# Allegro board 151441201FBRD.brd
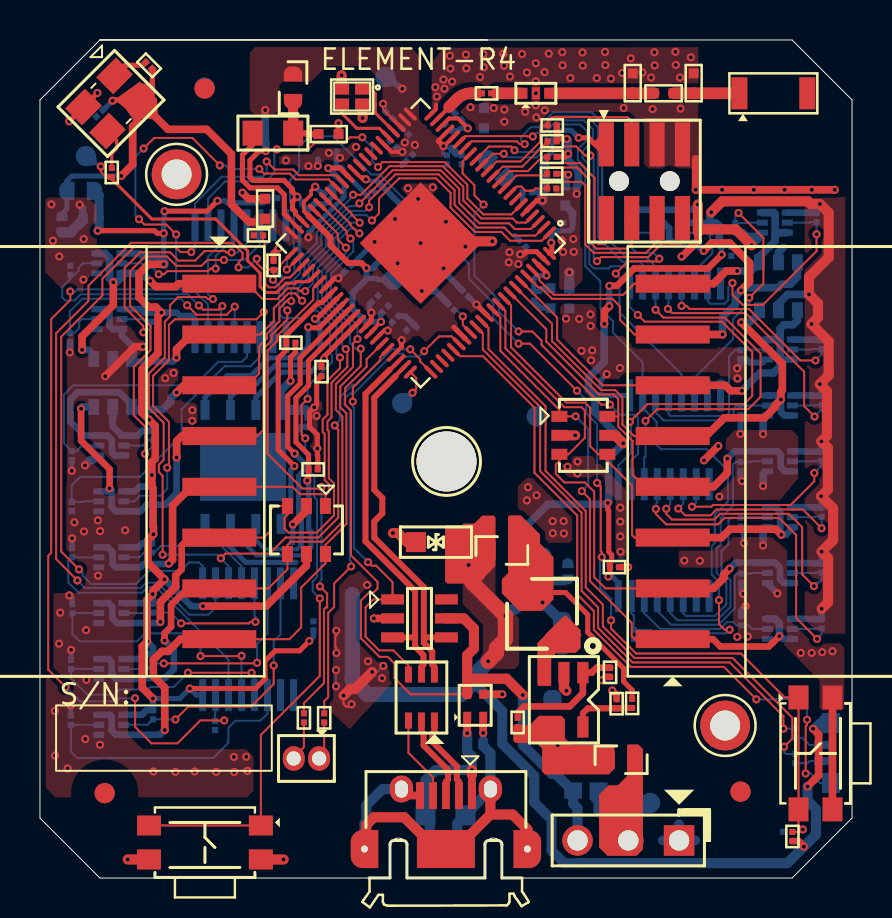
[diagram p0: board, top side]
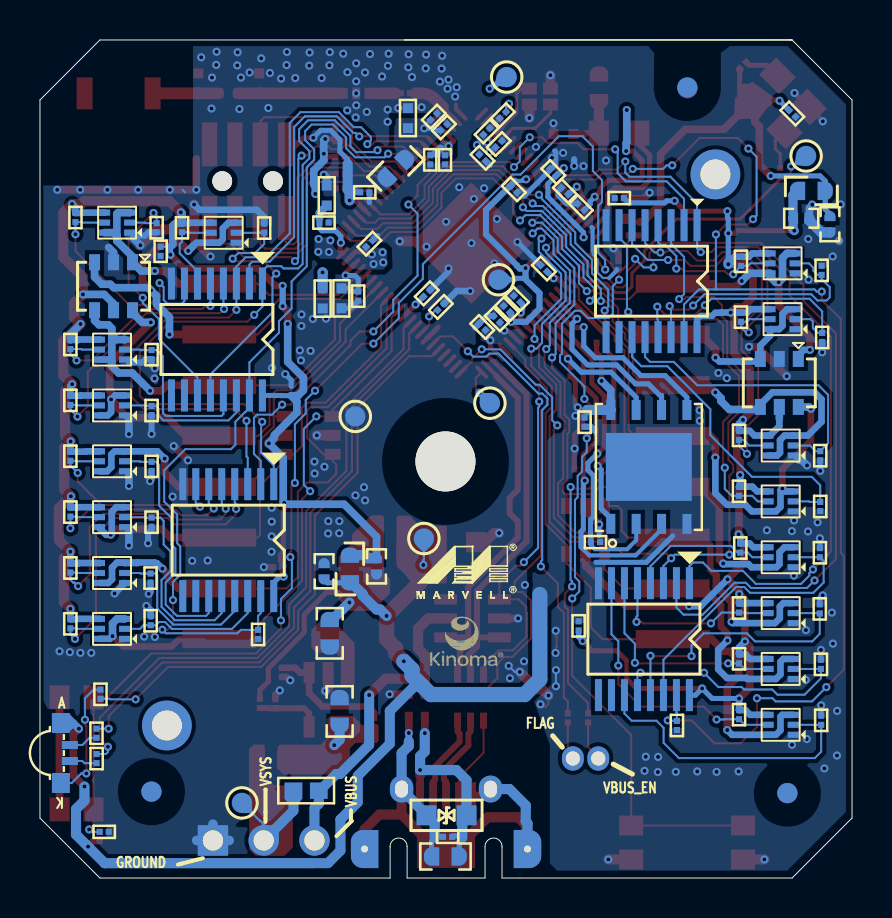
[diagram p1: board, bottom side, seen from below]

Outline 40.64 x 41.92 mm; copper layers: TOP, BOTTOM. Coordinates in mm from the lower left corner of the outline.
Outline path: 3,41.92 0,38.92 0,3 3,0 16.62,0 ; 3,41.92 22.4,41.92 3,41.92 ; 3,41.92 37.64,41.92 40.64,38.92 40.64,3 37.64,0 23.12,0

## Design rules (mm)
net group USB: nets CONN_DM CONN_DP
net group USB_D: nets USB_DM USB_DP

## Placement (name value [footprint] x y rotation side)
ANT1  2450AT18A100  [JOHANSON2450AT18A]  36.7 39.25 0 top
C1  2.2uF  [C0402]  25.55 29 270 bottom
C2  2.2uF  [C0402]  26.29 34.14 90 bottom
C3  0.1uF  [C0201]  24.38 34.3 180 bottom
C4  0.01uF  [C0201]  20.42 37.55 135 bottom
C5  10uF 6.3V X5R  [C0402]  22.23 38.01 90 bottom
C6  0.1uF  [C0201]  17.78 27.95 45 bottom
C7  0.1uF  [C0201]  24.16 31.73 135 bottom
C8  0.1uF  [C0201]  21.28 29.24 135 bottom
C9  0.1uF  [C0201]  16.76 28.97 45 bottom
C10  0.1uF  [C0201]  15.42 30.49 45 bottom
C12  10pF RF  [C0201]  22.35 39.25 180 top
C13  0.1uF  [C0201]  14.95 35.31 45 bottom
C14  0.1uF  [C0201]  18.51 27.57 45 bottom
C15  10uF 6.3V X5R  [C0402]  11.26 33.47 90 top
C16  2.2uF  [C0402]  26.49 28.99 270 bottom
C17  10uF 6.3V X5R  [C0402]  14.44 37.21 0 top
C18  1.0uF  [C0201]  20.37 35.93 270 bottom
C19  0.01uF  [C0201]  13.57 33.56 45 bottom
C20  1.0uF  [C0201]  17.27 28.46 45 bottom
C21  0.01uF  [C0201]  18.49 36.03 225 bottom
C22  0.01uF  [C0201]  17.68 36.71 135 bottom
C23  0.01uF  [C0201]  17.48 38.16 315 bottom
C24  0.1uF  [C0201]  13.38 22.8 270 bottom
C25  0.01uF  [C0201]  18.29 37.35 135 bottom
C26  0.01uF  [C0201]  21.11 35.93 270 bottom
C27  0.1uF  [C0201]  16.92 34.45 225 bottom
C28  0.1uF  [C0201]  14.38 34.37 45 bottom
C29  0.1uF  [C0201]  2.99 38.24 225 bottom
C48  0.1uF  [C0201]  20.24 2.06 180 bottom
C49  10uF 10V X6S  [C0603]  20.35 1.08 270 bottom
C50  4.7uF  [C0603]  25.64 8.33 180 bottom
C51  10uF 6.3V X5R  [C0603]  26.14 12.24 0 bottom
C84  *2.2uF  [C-0402]  26.42 15.34 180 bottom
C85  2.2uF  [C-0402]  23.8 15.59 0 bottom
C86  0.1uF  [C0201]  28.75 15.55 0 top
C87  0.1uF  [C0201]  34.6 31.35 270 bottom
C88  0.1uF  [C0201]  11.65 34.01 0 bottom
C89  0.1uF  [C0201]  13.68 12.61 90 bottom
C90  2.2uF  [C-0402]  2.54 33 270 bottom
C91  *2.2uF  [C-0402]  1.1 32.7 0 bottom
C92  0.1uF  [C0201]  24.71 29.11 270 bottom
C93  0.1uF  [C0201]  26.43 32.78 180 bottom
C94  0.1uF  [C0201]  37.42 2.31 180 bottom
C95  *0.1uF  [C0201]  11.69 30.65 90 top
C96  0.1uF  [C0201]  28.53 10.29 90 top
C98  0.01uF  [C0201]  20.93 38.08 135 bottom
CM1  CMC_2L_60R_600mA  [FIL-2X1_2-4]  21.78 8.64 90 top
CM2  CMC_3L  [TDK2520-3L]  19.09 9.03 90 top
D10  DIODE_LED_RGB_RA  [LED_RGB_RA]  39.54 6.25 270 bottom
FB1  FB/3A  [L-0603]  23.11 16.38 270 top
FB2  FB/3A  [L-0603]  29.09 5.91 90 top
FB7  FB/3A  [L-0603]  25.13 15.46 180 bottom
FB8  FB/3A  [L-0603]  2.03 34.37 90 bottom
FB9  FB/3A  [L-0603]  12.66 39.53 0 top
FB10  FB/3A  [L-0603]  22.83 35.49 45 bottom
FL1  -  [LFB182G45CL3D178]  24.82 39.25 180 top
J1  CON8A  [HDR050_4X2_SMT]  30.25 34.86 0 top
J2  *3PIN  [HDR0_1MILX3]  31.98 1.88 180 top
J3  USB MICRO-AB RCPT  [USB-MICRO-AB_FCI_RCPT_SMD5_RA]  20.32 0 0 top
J6  HDR1x8  [HDR1X8SMD_100MILRA]  31.66 20.84 270 top
J9  HDR1x8  [HDR1X8SMD_100MILRA]  8.98 20.84 90 top
J11  *CON2  [CON2_50]  13.97 5.98 180 top
L1  2.2nH  [L0402]  31.22 39.25 180 top
L2  *2.2nH  [L0402]  32.72 39.75 90 top
L3  2.2uH  [L0805]  11.66 37.26 0 top
L4  2.2uH  [CDRH2D14]  25.13 13.22 180 top
L5  2.2nH  [L0402]  29.67 39.75 90 top
MOV1  CDS305GTA  [D0603]  19.81 16.8 0 top
MOV3  CDS305GTA  [D0603]  20.29 3.14 180 bottom
NOREF  -  [unnamed]  8.24 39.49 0 top
NOREF#2  -  [unnamed]  3.24 4.25 0 top
NOREF#3  -  [unnamed]  34.29 7.63 0 top
NOREF#4  -  [unnamed]  35.06 4.32 0 top
NOREF#5  -  [unnamed]  20.35 20.84 0 top
NOREF#6  -  [#2]  38.95 40.61 0 top
NOREF#7  -  [unnamed]  6.84 35.2 0 top
NOREF#8  -  [unnamed]  35.06 4.32 180 bottom
NOREF#9  -  [unnamed]  8.24 39.54 180 bottom
NOREF#10  -  [unnamed]  3.24 4.25 180 bottom
Q1  FDY4000CZ  [SOT563]  37.03 12.46 0 bottom
Q2  FDY4000CZ  [SOT563]  37.03 15.26 0 bottom
Q3  FDY4000CZ  [SOT563]  37.03 18.05 0 bottom
Q4  FDY4000CZ  [SOT563]  37.03 20.85 0 bottom
Q5  FDY4000CZ  [SOT563]  37.03 23.64 0 bottom
Q6  FDY4000CZ  [SOT563]  37.03 26.43 0 bottom
Q7  FDY4000CZ  [SOT563]  31.45 32.28 0 bottom
Q8  FDY4000CZ  [SOT563]  36.78 32.78 0 bottom
Q9  FDY4000CZ  [SOT563]  3.47 30.75 0 bottom
Q10  FDY4000CZ  [SOT563]  3.48 27.96 0 bottom
Q11  FDY4000CZ  [SOT563]  3.57 21.63 0 bottom
Q12  FDY4000CZ  [SOT563]  3.57 18.84 0 bottom
Q13  FDY4000CZ  [SOT563]  3.57 16.05 0 bottom
Q14  FDY4000CZ  [SOT563]  3.57 13.25 0 bottom
Q15  FDY4000CZ  [SOT563]  3.57 10.46 0 bottom
Q16  FDY4000CZ  [SOT563]  3.57 7.66 0 bottom
R3  6.04k 1%  [R0201]  20.58 28.57 315 bottom
R4  51K  [R0201]  10.94 32.15 0 top
R5  51K  [R0201]  12.56 26.78 180 top
R6  51K  [R0201]  13.67 20.44 180 top
R7  51K  [R0201]  14.09 25.33 90 top
R25  1k  [R0201]  5.46 40.65 135 top
R27  10K  [R-0201]  25.62 36.07 180 top
R28  10K  [R-0201]  25.61 34.49 180 top
R29  10K  [R-0201]  25.63 36.85 180 top
R30  10K  [R-0201]  25.64 37.64 180 top
R36  10K  [R-0201]  25.61 35.23 0 top
R48  330R  [R0201]  37.81 7.24 90 bottom
R49  330R  [R0201]  37.81 5.97 90 bottom
R54  2.2K  [R0201]  37.66 2.08 90 top
R60  0R  [R-0603]  27.32 4.37 0 bottom
R63  10K  [R-0201]  23.91 7.78 90 top
R64  453K  [R0201]  29.63 8.73 270 top
R65  100K  [R0201]  28.86 8.72 90 top
R84  10K  [R-0201]  39.12 15.51 270 bottom
R85  10K  [R-0201]  39.12 18.31 270 bottom
R86  10K  [R-0201]  39.12 21.1 270 bottom
R87  10K  [R-0201]  35.11 15 90 bottom
R88  10K  [R-0201]  35.05 17.8 90 bottom
R89  10K  [R-0201]  35.05 20.59 90 bottom
R90  10K  [R-0201]  39.12 12.72 270 bottom
R91  10K  [R-0201]  35.1 12.87 270 bottom
R92  10K  [R-0201]  39.12 23.89 270 bottom
R93  10K  [R-0201]  39.12 26.69 270 bottom
R94  10K  [R-0201]  33.53 32.53 270 bottom
R95  10K  [R-0201]  38.86 33.04 270 bottom
R96  10K  [R-0201]  35.05 23.39 90 bottom
R97  10K  [R-0201]  35.05 26.18 90 bottom
R98  10K  [R-0201]  29.42 32.51 270 bottom
R99  10K  [R-0201]  34.8 32.53 90 bottom
R100  10K  [R-0201]  29.72 12.18 90 bottom
R101  10K  [R-0201]  5.56 30.85 270 bottom
R102  10K  [R-0201]  5.56 28.05 270 bottom
R103  10K  [R-0201]  5.66 22.14 270 bottom
R104  10K  [R-0201]  5.66 19.35 270 bottom
R105  10K  [R-0201]  1.5 27.04 90 bottom
R106  10K  [R-0201]  1.59 21.13 90 bottom
R107  10K  [R-0201]  1.59 18.59 90 bottom
R108  10K  [R-0201]  1.52 30.4 270 bottom
R109  10K  [R-0201]  5.59 16.51 270 bottom
R110  10K  [R-0201]  5.66 13.51 270 bottom
R111  10K  [R-0201]  5.66 10.97 270 bottom
R112  10K  [R-0201]  5.66 8.17 270 bottom
R113  10K  [R-0201]  1.61 16.27 270 bottom
R114  10K  [R-0201]  1.62 13.46 270 bottom
R115  10K  [R-0201]  1.56 10.69 270 bottom
R116  10K  [R-0201]  1.54 7.89 270 bottom
R117  10K  [R-0201]  8.76 7.63 90 bottom
R118  330R  [R0201]  37.61 9.19 270 bottom
R119  100R  [R0201]  14.22 8.01 90 top
R120  100R  [R0201]  13.21 8.01 90 top
R121  10K  [R-0201]  12.84 16.8 180 bottom
R128  22R  [R0201]  3.59 35.29 90 top
S1  SW_PB_RA_4P  [SW_WE_SPST_4P]  8.25 1.78 0 top
S2  SW_PB_RA_4P  [SW_WE_SPST_4P]  38.81 6.23 90 top
TP1  *T_POINT  [TP040]  30.53 3.76 180 bottom
TP2  *T_POINT  [TP040]  21.43 16.98 90 bottom
TP3  *T_POINT  [TP040]  24.86 23.09 180 bottom
TP4  *T_POINT  [TP040]  18.12 23.75 180 bottom
TP5  *T_POINT  [TP040]  2.3 36.12 180 bottom
TP6  *T_POINT  [TP040]  17.69 29.93 135 bottom
TP7  *T_POINT  [TP040]  17.28 40.07 135 bottom
U1  88MW302QFN88  [MRVL_QFN88LP40_10X10_NXU]  19.05 31.76 225 top
U2  W25Q32FVZPIG  [IC_WBOND_WSON8_ZP]  10.17 20.56 90 bottom
U7  AP3417C  [SOT23-5]  26.22 8.91 90 top
U8  IP4220CZ6  [IC_NXP_TSOP6]  18.99 12.99 270 top
U13  74HC4094  [TSSOP16]  31.22 16.9 0 bottom
U14  74HC4094  [TSSOP16]  31.78 26.94 0 bottom
U15  D5V0F4U6SO-7  [SC-74]  27.19 22.14 270 top
U16  D5V0F4U6SO-7  [SC-74]  36.96 29.6 0 bottom
U17  74HC4094  [TSSOP16]  10.03 29.86 0 bottom
U18  74HC4094  [TSSOP16]  10.41 11.95 0 bottom
U19  D5V0F4U6SO-7  [SC-74]  3.64 24.76 0 bottom
U20  D5V0F4U6SO-7  [SC-74]  13.34 17.41 180 top
Y1  38.4MHz +/-10ppm  [XTAL_TXC_SMD_1_6X1_2MM]  15.62 39.09 180 top
Y2  32.768KHz_3.3V_+/-25ppm  [XOSC_TXC_SMD_3_2X2_5MM]  3.56 38.75 225 top

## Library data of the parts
ANT1 = chip antenna
C1-C10 C12-C29 C48 C49 C86-C89 C92-C96 C98 = CAP_NP
C50 C51 = CAP NP_0
C84 C85 C90 C91 = CAP NP_2
CM1 = CMC_2L_1-2_3-4
CM2 = CMC_3L
D10 = DIODE_LED_RGB_RA
FB1 FB2 FB7-FB10 = FERRITE_BEAD_0
FL1 = RF_DEA162450BT-1298A1
J1 = CON8A
J2 = CON3
J3 = CON_MOLEX_USB-MICRO-AB_SMD
J6 J9 = CON8
J11 = CON2
L1-L5 = INDUCTOR
MOV1 MOV3 = MOV-small
Q1-Q16 = CMOS-DUAL
R3-R7 R25 R27-R30 R36 R48 R49 R54 R63-R65 R118-R120 R128 = RES
R60 R84-R99 R101-R116 = R_0
R100 R117 R121 = Res_0
S1 S2 = SW_PB_RA_4P
TP1-TP7 = T_POINT
U1 = 88MW302_QFN88L_1
U2 = IC_WBOND_SPI_FLASH_DQIO_WSON8
U7 = AP3417C
U8 = IC_NXP_IP4220CZ6_TSOP6
U13 U14 U17 U18 = 74HC4094
U15 U16 U19 U20 = CM1293A
Y1 = XTAL_TXC_SMD_1.6X1.2MM
Y2 = XOSC_TXC_3.2X2.5MM: Tolerance: TOL; User Part Number: 5044-001-002357

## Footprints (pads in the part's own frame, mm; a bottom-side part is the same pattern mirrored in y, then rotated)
C0201
  rect 0.305x0.305 smd: 1(-0.229,0) 2(0.229,0)
C0402
  rect 0.5x0.5 smd: 1(-0.5,0) 2(0.5,0)
C0603
  custom 0.191x0.191 smd: 1(0,-0.691) 2(0,0.691)
C-0402
  custom 0.126x0.126 smd: 1(0,-0.409) 2(0,0.409)
CDRH2D14
  rect 1.3x1.3 smd rot 45: 1(-1.061,1.061) 2(1.061,-1.061)
CON2_50
  oval 1.092x1.219 hole 0.711: 1(0,0) 2(1.27,0)
D0603
  rect 1.001x1.001 smd: 1(-1.001,0) 2(1.001,0)
FIL-2X1_2-4
  rect 0.45x0.4 smd: 1(-0.55,0.4) 2(0.55,0.4) 3(0.55,-0.4) 4(-0.55,-0.4)
HDR0_1MILX3
  rect 1.524x1.524 hole 1.016: 1(0,0)
  round 1.524 hole 1.016: 2(2.54,0) 3(5.08,0)
HDR1X8SMD_100MILRA
  rect 0.9x3.7 smd: 1(8.89,0) 2(6.35,0) 3(3.81,0) 4(1.27,0) 5(-1.27,0) 6(-3.81,0) 7(-6.35,0) 8(-8.89,0)
HDR050_4X2_SMT
  round 0.991 hole 0.991 unplated: (-1.27,0) (1.27,0)
  rect 0.76x2.2 smd: 1(-1.905,1.841) 2(-1.905,-1.841) 3(-0.635,1.841) 4(-0.635,-1.841) 5(0.635,1.841) 6(0.635,-1.841) 7(1.905,1.841) 8(1.905,-1.841)
IC_NXP_TSOP6
  rect 0.508x1.143 smd: 1(-0.95,-1.349) 2(0,-1.349) 3(0.95,-1.349) 4(0.95,1.349) 5(0,1.349) 6(-0.95,1.349)
IC_WBOND_WSON8_ZP
  rect 1x0.45 smd: 1(-2.85,1.905) 2(-2.85,0.635) 3(-2.85,-0.635) 4(-2.85,-1.905) 5(2.85,-1.905) 6(2.85,-0.635) 7(2.85,0.635) 8(2.85,1.905)
  rect 3.4x4.3 smd: 9(0,0)
JOHANSON2450AT18A
  rect 0.8x1.6 smd: 1(-1.7,0) 2(1.7,0)
L0402
  rect 0.5x0.5 smd: 1(-0.5,0) 2(0.5,0)
L0805
  rect 1.001x1.25 smd: 1(-1.016,0) 2(1.016,0)
L-0603
  custom 0.191x0.191 smd: 1(0,-0.691) 2(0,0.691)
LED_RGB_RA
  rect 1.001x0.899 smd: 1(1.5,-0.05) 2(-1.5,-0.05)
  rect 0.399x0.8 smd: 3(-0.4,0.4) 4(0.4,0.4)
LFB182G45CL3D178
  rect 0.28x0.55 smd: 1(0.56,0) 3(-0.56,0)
  rect 0.4x0.6 smd: 2(0,0)
MRVL_QFN88LP40_10X10_NXU
  oval 0.85x0.2 smd: 1(-4.925,4.2) 2(-4.925,3.8) 3(-4.925,3.4) 4(-4.925,3) 5(-4.925,2.6) 6(-4.925,2.2) 7(-4.925,1.8) 8(-4.925,1.4) 9(-4.925,1) 10(-4.925,0.6) 11(-4.925,0.2) 12(-4.925,-0.2) 13(-4.925,-0.6) 14(-4.925,-1) 15(-4.925,-1.4) 16(-4.925,-1.8) 17(-4.925,-2.2) 18(-4.925,-2.6) 19(-4.925,-3) 20(-4.925,-3.4) 21(-4.925,-3.8) 22(-4.925,-4.2) 45(4.925,-4.2) 46(4.925,-3.8) 47(4.925,-3.4) 48(4.925,-3) 49(4.925,-2.6) 50(4.925,-2.2) 51(4.925,-1.8) 52(4.925,-1.4) 53(4.925,-1) 54(4.925,-0.6) 55(4.925,-0.2) 56(4.925,0.2) 57(4.925,0.6) 58(4.925,1) 59(4.925,1.4) 60(4.925,1.8) 61(4.925,2.2) 62(4.925,2.6) 63(4.925,3) 64(4.925,3.4) 65(4.925,3.8) 66(4.925,4.2)
  oval 0.2x0.85 smd: 23(-4.2,-4.925) 24(-3.8,-4.925) 25(-3.4,-4.925) 26(-3,-4.925) 27(-2.6,-4.925) 28(-2.2,-4.925) 29(-1.8,-4.925) 30(-1.4,-4.925) 31(-1,-4.925) 32(-0.6,-4.925) 33(-0.2,-4.925) 34(0.2,-4.925) 35(0.6,-4.925) 36(1,-4.925) 37(1.4,-4.925) 38(1.8,-4.925) 39(2.2,-4.925) 40(2.6,-4.925) 41(3,-4.925) 42(3.4,-4.925) 43(3.8,-4.925) 44(4.2,-4.925) 67(4.2,4.925) 68(3.8,4.925) 69(3.4,4.925) 70(3,4.925) 71(2.6,4.925) 72(2.2,4.925) 73(1.8,4.925) 74(1.4,4.925) 75(1,4.925) 76(0.6,4.925) 77(0.2,4.925) 78(-0.2,4.925) 79(-0.6,4.925) 80(-1,4.925) 81(-1.4,4.925) 82(-1.8,4.925) 83(-2.2,4.925) 84(-2.6,4.925) 85(-3,4.925) 86(-3.4,4.925) 87(-3.8,4.925) 88(-4.2,4.925)
  rect 4.3x4.3 smd: 89(0,0)
R0201
  rect 0.305x0.305 smd: 1(-0.229,0) 2(0.229,0)
R-0201
  rect 0.305x0.305 smd: 1(-0.229,0) 2(0.229,0)
R-0603
  rect 0.889x0.813 smd: 1(-0.635,0) 2(0.635,0)
SC-74
  rect 0.55x0.8 smd: 1(-0.95,-1.2) 2(0,-1.2) 3(0.95,-1.2) 4(0.95,1.2) 5(0,1.2) 6(-0.95,1.2)
SOT23-5
  rect 1.069x0.559 smd: 1(1.359,-0.95) 2(1.359,0) 3(1.359,0.95) 4(-1.359,0.95) 5(-1.359,-0.95)
SOT563
  rect 0.55x0.305 smd: 1(-0.625,0.5) 2(-0.625,0) 3(-0.625,-0.5) 4(0.625,-0.5) 5(0.625,0) 6(0.625,0.5)
SW_WE_SPST_4P
  rect 1.2x1 smd: 1(2.8,0.85) 2(-2.8,0.85) 3(2.8,-0.85) 4(-2.8,-0.85)
TDK2520-3L
  rect 0.8x0.35 smd: 1(-1.151,-0.65) 2(-1.151,0) 3(-1.151,0.65) 4(1.151,0.65) 5(1.151,0) 6(1.151,-0.65)
TP040
  round 1.016 smd: 1(0,0)
TSSOP16
  rect 0.35x1.6 smd: 1(-2.276,-2.799) 2(-1.626,-2.799) 3(-0.975,-2.799) 4(-0.325,-2.799) 5(0.325,-2.799) 6(0.975,-2.799) 7(1.626,-2.799) 8(2.276,-2.799) 9(2.276,2.799) 10(1.626,2.799) 11(0.975,2.799) 12(0.325,2.799) 13(-0.325,2.799) 14(-0.975,2.799) 15(-1.626,2.799) 16(-2.276,2.799)
unnamed
  round 1.016 smd: (0,0)
USB-MICRO-AB_FCI_RCPT_SMD5_RA
  rect 0.399x1.349 smd: 1(1.301,4.125) 2(0.65,4.125) 3(0,4.125) 4(-0.65,4.125) 5(-1.301,4.125)
  oval 1.168x1.346 hole 0.65x0.851: 6(-2.225,4.45) 7(2.225,4.45)
  custom 0.344x0.344 hole 0.8x1.5: 8(-4.075,1.45) 9(4.075,1.45)
  rect 2.901x1.9 smd: 10(0,1.45)
XOSC_TXC_SMD_3_2X2_5MM
  rect 1.4x1.2 smd: 1(-1.1,-0.85) 2(1.1,-0.85) 3(1.1,0.85) 4(-1.1,0.85)
XTAL_TXC_SMD_1_6X1_2MM
  rect 0.75x0.6 smd: 1(-0.526,-0.399) 2(0.526,-0.399) 3(0.526,0.399) 4(-0.526,0.399)

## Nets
GND: C1.2 C2.2 C3.2 C4.2 C5.2 C6.2 C7.2 C8.2 C9.2 C10.2 C13.2 C14.2 C15.2 C16.2 C17.2 C18.2 C19.2 C20.2 C21.2 C22.2 C23.2 C24.2 C25.2 C26.2 C27.2 C28.2 C29.2 C50.2 C51.2 C84.2 C85.2 C86.2 C87.2 C88.2 C89.2 C90.2 C91.2 C92.2 C93.2 C94.2 C95.2 C96.1 C98.2 CM1.3(OUT2) FL1.2(GND) J1.5 J1.7 J2.1 L2.2 L5.2 MOV1.1 Q1.1(S) Q2.1(S) Q3.1(S) Q4.1(S) Q5.1(S) Q6.1(S) Q7.1(S) Q8.1(S) Q9.1(S) Q10.1(S) Q11.1(S) Q12.1(S) Q13.1(S) Q14.1(S) Q15.1(S) Q16.1(S) R3.1 R36.2 R65.2 R87.1 R88.1 R89.1 R91.1 R96.1 R97.1 R98.1 R99.1 R100.1 R105.1 R106.1 R107.1 R108.1 R113.1 R114.1 R115.1 R116.1 R117.1 R121.2 S1.3 S1.4 S2.3 S2.4 TP3.1(TP) U1.22(NC) U1.89(EPAD) U2.4(GND) U2.9(EPAD) U7.2(GND) U8.2(GND) U13.8(GND) U14.8(GND) U15.2(NV) U16.2(NV) U17.8(GND) U18.8(GND) U19.2(NV) U20.2(NV) Y1.2(GND#2) Y1.4(GND#4) Y2.2(GND)
GND_EN1: Q1.2(G) R91.2 U13.14(QP4)
GND_EN2: Q2.2(G) R87.2 U13.13(QP5)
GND_EN3: Q3.2(G) R88.2 U13.12(QP6)
GND_EN4: Q4.2(G) R89.2 U13.11(QP7)
GND_EN5: Q5.2(G) R96.2 U14.14(QP4)
GND_EN6: Q6.2(G) R97.2 U14.13(QP5)
GND_EN7: Q7.2(G) R98.2 U14.12(QP6)
GND_EN8: Q8.2(G) R99.2 U14.11(QP7)
GND_EN9: Q9.2(G) R108.2 U17.14(QP4)
GND_EN10: Q10.2(G) R105.2 U17.13(QP5)
GND_EN11: Q11.2(G) R106.2 U17.12(QP6)
GND_EN12: Q12.2(G) R107.2 U17.11(QP7)
GND_EN13: Q13.2(G) R113.2 U18.14(QP4)
GND_EN14: Q14.2(G) R114.2 U18.13(QP5)
GND_EN15: Q15.2(G) R115.2 U18.12(QP6)
GND_EN16: Q16.2(G) R116.2 U18.11(QP7)
GND_OTG_CONN: C48.1 C49.1 CM1.4(IN2) J3.5(GND) J3.6(SHIELD1) J3.7(SHIELD2) J3.8(SHIELD3) J3.9(SHIELD4) J3.10(SHIELD5) MOV3.1
V1P1: C20.1 C27.1 C28.1 TP6.1(TP) U1.33(VDD11#33) U1.41(LDO11_VOUT) U1.59(VDD11#59)
V1P8: C18.1 C19.1 C21.1 C22.1 C23.1 C25.1 C26.1 FB9.2 TP7.1(TP) U1.18(AVDD18#18) U1.19(AVDD18#19) U1.23(AVDD18#23) U1.24(AVDD18#24) U1.25(AVDD18#25) U1.28(AVDD18#28) U1.42(LDO11_V18)
V1P8O: C17.1 FB9.1 L3.2
V3P3: C3.1 C6.1 C7.1 C8.1 C9.1 C10.1 C13.1 C14.1 C15.1 C16.1 C24.1 C29.1 C84.1 C91.1 D10.2(ANODE) FB1.1 FB7.1 FB8.1 FB10.2 J1.1 MOV1.2 R4.1 R5.1 R6.1 R7.1 R25.1 R27.1 R28.1 R29.1 R30.1 R54.1 TP2.1(TP) U1.5(VDDIO_0) U1.34(VDDIO_1) U1.44(VBAT_IN#44) U1.51(VDDIO_AON) U1.58(VDDIO_2) U1.60(VTR_VDD33) U1.63(USB_AVDD33) U1.73(VDDIO_3#73) U1.77(VDDIO_3#77) U1.87(VBAT_IN#87) U2.8(VCC) Y2.4(VDD)
V3P3_EN: C96.2 R63.2 U7.1(EN)
V3P3_FB: R64.2 R65.1 U7.5(FB)
V3P3_OUT: C51.1 FB1.2 L4.2 R64.1
V5P0_VIN: C50.1 FB2.2 R63.1 U7.4(VIN)
VBUS_OTG: CM1.2(OUT1) J2.3 R60.1 U1.61(USB_VBUS) U8.5(VP)
VBUS_OTG_CONN: C48.2 C49.2 CM1.1(IN1) J3.1(VBUS) MOV3.2
VCC_FLEX1: C85.1 C86.1 C87.1 FB7.2 Q1.4(S) Q2.4(S) Q3.4(S) Q4.4(S) Q5.4(S) Q6.4(S) Q7.4(S) Q8.4(S) R84.1 R85.1 R86.1 R90.1 R92.1 R93.1 R94.1 R95.1 U13.16(VCC) U14.16(VCC) U15.5(VP) U16.5(VP)
VCC_FLEX2: C88.1 C89.1 C90.1 FB8.2 Q9.4(S) Q10.4(S) Q11.4(S) Q12.4(S) Q13.4(S) Q14.4(S) Q15.4(S) Q16.4(S) R101.1 R102.1 R103.1 R104.1 R109.1 R110.1 R111.1 R112.1 U17.16(VCC) U18.16(VCC) U19.5(VP) U20.5(VP)
VDD11_F_88: C2.1 C93.1 U1.88(FLY11)
VDD18_F_86: C1.1 C92.1 U1.86(FLY18)
VDD33_20: C4.1 C5.1 C98.1 FB10.1 U1.20(AVDD33)
CLK32K: R128.2 Y2.3(OUT)
CONN_DM: CM2.1(IN1) J3.2(D-)
CONN_DP: CM2.2(OUT1) J3.3(D+)
CONN_ID: CM2.3(OUT2) J3.4(ID)
CP1: U1.16(GPIO_14) U13.3(CP) U14.3(CP)
CP2: U1.67(GPIO_34) U17.3(CP) U18.3(CP)
D_1_4: U1.15(GPIO_13) U13.2(D)
D_5_8: U1.17(GPIO_15) U14.2(D)
D_9_12: U1.6(GPIO_4) U17.2(D)
D_13_16: U1.47(GPIO_23) U18.2(D)
EN_32K: R25.2 Y2.1(EC)
GPIO_5: U1.7(GPIO_5)
GPIO_24: U1.48(GPIO_24)
GPIO_25: R128.1 TP5.1(TP) U1.49(GPIO_25)
GPIO_27: TP4.1(TP) U1.66(GPIO_27)
GPIO_35: U1.68(GPIO_35)
GPIO_36: U1.69(GPIO_36)
GPIO_37: U1.70(GPIO_37)
ISENSE: R3.2 U1.74(ISENSE)
LED1: R48.2 U1.75(GPIO_40)
LED2: R49.2 U1.76(GPIO_41)
LED3: R118.2 U1.71(GPIO_38)
MCI_TCK: J1.4 R36.1 U1.9(GPIO_7)
MCI_TDI: J1.8 R29.2 U1.11(GPIO_9)
MCI_TDO: J1.6 R28.2 U1.8(GPIO_6)
MCI_TMS: J1.2 R27.2 U1.10(GPIO_8)
MCI_TRST: J1.3 R30.2 U1.12(GPIO_10)
OE1: R100.2 U1.13(GPIO_11) U13.15(OE) U14.15(OE)
OE2: R117.2 U1.36(GPIO_17) U17.15(OE) U18.15(OE)
PIN1: J6.1 Q1.3(D) Q1.6(D) U1.78(GPIO_42) U15.1(CH1)
PIN2: J6.2 Q2.3(D) Q2.6(D) U1.79(GPIO_43) U15.3(CH2)
PIN3: J6.3 Q3.3(D) Q3.6(D) U1.80(GPIO_44) U15.4(CH3)
PIN4: J6.4 Q4.3(D) Q4.6(D) U1.81(GPIO_45) U15.6(CH4)
PIN5: J6.5 Q5.3(D) Q5.6(D) U1.82(GPIO_46) U16.6(CH4)
PIN6: J6.6 Q6.3(D) Q6.6(D) U1.83(GPIO_47) U16.4(CH3)
PIN7: J6.7 Q7.3(D) Q7.6(D) U1.84(GPIO_48) U16.3(CH2)
PIN8: J6.8 Q8.3(D) Q8.6(D) U1.85(GPIO_49) U16.1(CH1)
PIN9: J9.1 Q9.3(D) Q9.6(D) U1.1(GPIO_0) U19.1(CH1)
PIN10: J9.2 Q10.3(D) Q10.6(D) U1.2(GPIO_1) U19.3(CH2)
PIN11: J9.3 Q11.3(D) Q11.6(D) U1.3(GPIO_2) U19.4(CH3)
PIN12: J9.4 Q12.3(D) Q12.6(D) U1.4(GPIO_3) U19.6(CH4)
PIN13: J9.5 Q13.3(D) Q13.6(D) U1.37(GPIO_18) U20.1(CH1)
PIN14: J9.6 Q14.3(D) Q14.6(D) U1.38(GPIO_19) U20.3(CH2)
PIN15: J9.7 Q15.3(D) Q15.6(D) U1.39(GPIO_20) U20.4(CH3)
PIN16: J9.8 Q16.3(D) Q16.6(D) U1.40(GPIO_21) U20.6(CH4)
PWR_EN1: Q1.5(G) R90.2 U13.4(QP0)
PWR_EN2: Q2.5(G) R84.2 U13.5(QP1)
PWR_EN3: Q3.5(G) R85.2 U13.6(QP2)
PWR_EN4: Q4.5(G) R86.2 U13.7(QP3)
PWR_EN5: Q5.5(G) R92.2 U14.4(QP0)
PWR_EN6: Q6.5(G) R93.2 U14.5(QP1)
PWR_EN7: Q7.5(G) R94.2 U14.6(QP2)
PWR_EN8: Q8.5(G) R95.2 U14.7(QP3)
PWR_EN9: Q9.5(G) R101.2 U17.4(QP0)
PWR_EN10: Q10.5(G) R102.2 U17.5(QP1)
PWR_EN11: Q11.5(G) R103.2 U17.6(QP2)
PWR_EN12: Q12.5(G) R104.2 U17.7(QP3)
PWR_EN13: Q13.5(G) R109.2 U18.4(QP0)
PWR_EN14: Q14.5(G) R110.2 U18.5(QP1)
PWR_EN15: Q15.5(G) R111.2 U18.6(QP2)
PWR_EN16: Q16.5(G) R112.2 U18.7(QP3)
QSPI_CLK: U1.53(GPIO_29) U2.6(CLK)
QSPI_D0: U1.54(GPIO_30) U2.5(DI)
QSPI_D1: R121.1 U1.55(GPIO_31) U2.2(DO)
QSPI_D2: R6.2 U1.56(GPIO_32) U2.3(W\P\)
QSPI_D3: R7.2 U1.57(GPIO_33) U2.7(H\O\L\D\)
QSPI_SSN: R5.2 U1.52(GPIO_28) U2.1(C\S\)
RESETN: C95.1 R4.2 S1.1 S1.2 U1.45(RESETN)
RF_TX-RX: C12.2 U1.21(RF_TR)
STR1: U1.14(GPIO_12) U13.1(STR) U14.1(STR)
STR2: U1.35(GPIO_16) U17.1(STR) U18.1(STR)
SW3P3: L4.1 U7.3(LX)
USB_DM: CM2.6(IN6) U1.65(USB_DM) U8.4(IO3)
USB_DP: CM2.5(IN5) U1.64(USB_DP) U8.3(IO2)
USB_DRVBUS: R120.2 U1.50(GPIO_26)
USB_ID: CM2.4(IN2) U1.62(USB_ID) U8.1(IO1)
USB_OTG_POWER_FAULT: R119.2 U1.72(GPIO_39)
VSYS_IN: FB2.1 J2.2 R60.2 TP1.1(TP)
WAKEUP0: C94.1 R54.2 S2.1 S2.2 U1.46(GPIO_22)
XTAL_IN: U1.26(XTAL_IN) Y1.1(IN)
XTAL_OUT: U1.27(XTAL_OUT) Y1.3(OUT)
N04866: L3.1 U1.43(BUCK18_VX)
N14504: C12.1 FL1.1(IN)
N14557: ANT1.1 L1.1 L2.1
N16809573: D10.4(B) R49.1
N16809863: D10.1(R) R118.1
N16809865: D10.3(G) R48.1
N16909824: J11.1 R119.1
N16909825: J11.2 R120.1
N16943358: FL1.3(OUT) L1.2 L5.1

Pads without a net: ANT1 2; U1 29 30 31 32; U8 6; U13 9 10; U14 9 10; U17 9 10; U18 9 10

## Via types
v1: diameter 0.406, hole 0.203, TOP to BOTTOM, 433 vias

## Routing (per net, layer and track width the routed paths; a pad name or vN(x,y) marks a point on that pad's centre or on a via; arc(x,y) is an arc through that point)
GND: length 95
  TOP w0.102: v1(15.19,9.13) 15.19,8.71 15.34,8.56 15.46,8.56 v1(15.59,8.69) ; v1(14.83,12.37) 14.83,12.12 14.78,12.07 14.78,11.57 14.84,11.51 v1(14.84,11.26) ; 32.79,36 32.82,35.98 ; v1(16.63,10.31) 16.73,10.31
  TOP w0.203: U1.22 19.82,38.47 19.82,38.69
  TOP w0.254: R36.2 26.39,35.23 v1(26.44,35.18) ; v1(1.46,37.85) Y2.2 v1(2.88,39.27)
  TOP w0.305: C17.2 v1(14.94,37.76) ; v1(11.94,31.5) 11.69,31.25 C95.2
  TOP w0.33: R65.2 28.86,9.16 v1(28.64,9.38) ; C96.1 28.52,10.06 28.29,10.06 v1(28.12,9.89) ; C86.2 v1(29.44,15.55)
  TOP w0.381: CM1.3 v1(23.14,9.19) ; 32.93,32.31 32.93,31.85 32.91,31.85 32.14,31.09 v1(32.11,31.09) ; C15.2 10.44,33.97 v1(10.13,34.28) ; v1(39.78,34.43) v1(38.63,34.43) v1(37.26,34.43) v1(35.73,34.43) v1(34.14,34.43) v1(32.82,34.43) 32.82,35.98 ; U8.2 v1(16.71,12.99) ; S2.4 S2.3 ; v1(33.23,20.89) v1(33.95,21.61) ; v1(12.66,17.69) 13.34,18.36 U20.2 ; v1(5.15,26.58) 4.74,26.58 v1(3.27,25.1)
  TOP w0.5: MOV1.1 18.37,16.8 17.92,17.26 v1(17.66,17.26)
  TOP w0.508: v1(26.35,9.37) 26.22,9.49 U7.2 ; v1(35.61,31.65) 34.82,32.45 33.06,32.45 32.93,32.31 v1(32.93,33.69) ; S1.4 v1(4.39,0.93) ; v1(22.63,31.85) 21.56,31.85 v1(21.29,31.58) ; Y1.2 v1(15.1,40.16) ; U15.2 v1(26.78,22.14) ; S1.3 v1(12.19,0.93) ; Y1.4 v1(16.15,38.02) ; v1(16.63,10.31) 15.77,9.45 15.52,9.45 v1(15.19,9.13)
  BOTTOM w0.102: 16.43,34.1 16.42,34.1 ; 12.98,31.34 12.98,31.34 12.98,31.19 12.74,30.95 12.74,30.29 12.46,30.01 12.16,30.01 ; v1(16.63,10.31) 16.88,10.31 v1(17.18,10.61) ; v1(23.24,38.44) 23.27,38.41 ; 16.67,34.42 16.55,34.42 16.47,34.34 ; 21.67,38.59 21.59,38.67 ; 14.89,36.37 14.8,36.46 ; 33.51,34.43 33.38,34.3 ; v1(14.82,9.59) v1(14.82,10.4) ; 24.13,33.77 24.16,33.79 ; 8.97,17.12 8.91,17.12
  BOTTOM w0.203: 12.16,30.01 11.77,30.39 11.77,30.46 ; 13.04,32.57 12.98,32.51 12.98,31.34
  BOTTOM w0.254: 28.07,24.58 28.07,24.91 v1(28.36,25.21) ; v1(1.47,14.14) 1.62,13.99 R114.1 ; 14.73,34.16 14.29,33.73 C19.2 ; R113.1 v1(1.61,16.99) ; C10.2 v1(16.75,31.82) ; 14.57,34.49 14.73,34.33 ; C92.2 25.09,28.5 C1.2 ; 18.11,35.64 18.11,35.65 C21.2 ; 12.66,17.13 v1(12.66,17.69) ; 24.16,33.79 C3.2 ; R106.1 v1(1.59,20.37) ; 16.42,34.1 14.82,35.69 14.82,36.31 14.89,36.37 ; 8.97,17.12 10.29,15.79 12.82,15.79 ; R115.1 v1(1.56,11.41) ; C7.2 23.75,32.14 ; R116.1 v1(1.54,8.64)
  BOTTOM w0.305: R87.1 35.11,14.31 v1(35.2,14.21) ; 18.67,27.73 C14.2 ; 18.67,27.73 18.28,28.11 C6.2 ; 18.67,27.73 18.86,27.54 ; 13.91,35.95 v1(13.91,35.62) ; v1(34.89,25.5) 35.05,25.66 R97.1 35.36,25.95 35.53,25.78 36.19,25.78 ; R89.1 35.05,19.93 v1(35.13,19.86) ; 12.87,22.37 13.08,22.57 C24.2 ; v1(20.2,30.49) 20.2,30.33 20.92,29.61 20.92,29.6 C8.2 ; R88.1 35.05,17.43 35.23,17.25 v1(35.23,16.75) ; R99.1 35.21,32.3 35.38,32.13 35.93,32.13 ; v1(35.05,22.21) R96.1
  BOTTOM w0.33: Q2.1 36.41,14.73 v1(36.91,14.23) ; v1(35.32,13.61) 35.1,13.39 R91.1 ; R105.1 v1(1.5,26.29) ; R3.1 19.79,29.36 v1(19.11,29.36) ; R98.1 29.42,33.06 29.79,33.43 32.67,33.43 v1(32.93,33.69)
  BOTTOM w0.381: C90.2 2.13,33.51 1.99,33.65 v1(1.99,33.68) ; 36.19,20.2 v1(36.19,19.61) ; v1(2.25,20.64) 2.53,20.92 2.66,20.92 2.72,20.98 ; 36.19,22.99 v1(36.19,22.21) ; v1(26.44,35.18) 26.29,35.03 C2.2 ; 37.21,31.55 36.96,31.3 U16.2 ; 36.19,17.4 v1(36.19,16.63) ; v1(35.61,31.65) 35.93,31.97 35.93,32.13
  BOTTOM w0.483: J2.1 31.98,2.69 ; J2.1 32.8,1.88 ; J2.1 31.17,1.88
  BOTTOM w0.508: C90.2 2.13,32.89 1.53,32.29 1.11,32.29 C91.2
  vias: v1(0.57,33.7) v1(0.65,31.87) v1(0.74,8.36) v1(0.75,6.13) v1(0.97,31.09) v1(1.01,13.28) v1(0.95,11.72) v1(1.38,5.48) v1(1.72,17.79) v1(2.19,31.97) v1(2.18,29.93) v1(2.2,17.34) v1(2.31,12.4) v1(2.32,9.91) v1(2.27,6.95) v1(2.9,17.89) v1(2.91,15.12) v1(3.01,17.35) v1(3,6.66) v1(4.26,17.4) v1(5.68,5.33) v1(6.27,25) v1(6.69,25.27) v1(6.78,5.31) v1(7.63,23.4) v1(7.61,22.87) v1(7.75,5.33) v1(8.82,5.31) v1(9.71,6.06) v1(9.72,5.3) v1(10.32,6.07) v1(10.38,5.36) v1(12.31,35.89) v1(13.44,35.61) v1(14.46,36.27) v1(15.02,36.02) v1(15.82,36.57) v1(16.37,14.66) v1(16.42,10.84) v1(17.12,10) v1(17.77,32.97) v1(17.9,30.75) v1(18.41,34.5) v1(18.92,33.97) v1(19.05,31.76) v1(19.66,34.55) v1(19.79,39.56) v1(19.86,39.09) v1(20.19,39.94) v1(20.24,39.48) v1(20.32,32.83) v1(20.51,41.13) v1(20.54,40.49) v1(20.62,39.84) v1(21.32,41.19) v1(21.33,40.5) v1(21.54,38.56) v1(22.02,40.07) v1(22.19,41.21) v1(22.21,40.55) v1(22.71,38.52) v1(23.19,41.23) v1(23.23,40.63) v1(23.24,37.83) v1(23.52,40.09) v1(24.12,41.22) v1(24.28,38.32) v1(24.37,40.3) v1(24.42,19.55) v1(24.37,18.89) v1(24.82,40.75) v1(24.82,39.85) v1(24.82,39.25) v1(24.81,38.65) v1(24.84,38.05) v1(24.85,19.14) v1(25.25,40.31) v1(25.26,38.4) v1(25.46,41.23) v1(25.66,17.85) v1(25.67,17.25) v1(26.14,41.31) v1(26.15,40.66) v1(26.21,17.85) v1(26.22,17.24) v1(26.32,27.98) v1(26.4,20.57) v1(26.54,40.02) v1(26.9,20.83) v1(26.89,20.24) v1(26.99,27.97) v1(27.1,26.37) v1(27.15,41.3) v1(27.16,40.64) v1(27.55,28.19) v1(27.56,27.61) v1(27.64,26.4) v1(27.58,25.89) v1(27.86,40.02) v1(28.28,41.32) v1(28.3,40.67) v1(28.57,39.99) v1(29.02,25.51) v1(29.13,40.27) v1(29.04,18.52) v1(29.04,17.83) v1(29.04,17.09) v1(29.05,16.32) v1(29.21,38.52) v1(29.57,41) v1(30.15,40.29) v1(30.58,40.04) v1(30.66,38.47) v1(30.75,41.3) v1(30.77,40.65) v1(31.8,41.33) v1(31.82,40.67) v1(32.03,40.04) v1(32.05,38.49) v1(32.25,15.88) v1(32.57,41.05) v1(33.02,15.86) v1(34,19.08) v1(34.9,24.99) v1(34.89,12.06) v1(35.43,12.08) v1(38.07,11.26) v1(38.62,11.26) v1(39.14,11.3) v1(39.66,11.34)
GND_EN1: length 7.6
  BOTTOM w0.102: Q1.2 35.63,12.46 35.46,12.64 R91.2 34.84,12.64 34.68,12.81 34.38,12.81 34.04,12.46 31.03,12.46 30.24,13.25 U13.14
GND_EN2: length 8.6
  BOTTOM w0.102: Q2.2 35.63,15.26 35.61,15.23 R87.2 34.87,15.23 34.77,15.13 34.77,13.48 33.96,12.67 31.58,12.67 30.89,13.37 U13.13
GND_EN3: length 11
  BOTTOM w0.102: Q3.2 35.4,18.05 35.37,18.03 R88.2 34.61,18.03 34.45,17.87 34.45,16.69 34.11,16.34 34.11,15.35 34.56,14.9 34.56,13.57 33.89,12.9 31.9,12.9 31.54,13.25 U13.12
GND_EN4: length 12.6
  BOTTOM w0.102: U13.11 32.19,13.25 32.33,13.11 33.78,13.11 34.35,13.68 34.35,14.79 33.86,15.27 33.86,16.48 34.07,16.69 34.07,18.02 34.68,18.62 34.68,20.67 34.83,20.82 R89.2 35.61,20.82 35.63,20.85 Q4.2
GND_EN5: length 7.1
  BOTTOM w0.102: Q5.2 35.38,23.64 35.36,23.61 R96.2 34.85,23.61 34.71,23.47 34.71,23.13 34.47,22.89 31.21,22.89 30.81,23.29 U14.14
GND_EN6: length 9
  BOTTOM w0.102: U14.13 31.46,23.21 31.55,23.11 34.33,23.11 34.49,23.27 34.49,26.1 34.8,26.41 R97.2 35.6,26.41 35.62,26.43 Q6.2
GND_EN7: length 13.8
  TOP w0.102: v1(28.82,30.24) 29.43,30.85 30.38,30.85 30.39,30.85 30.86,30.85 v1(31,30.98)
  BOTTOM w0.102: v1(31,30.98) 30.72,31.26 29.88,31.26 29.42,31.72 R98.2 29.62,32.28 29.63,32.28 Q7.2 ; v1(28.82,30.24) 29,30.05 29,28.3 32.11,25.19 U14.12
GND_EN8: length 13
  TOP w0.102: v1(35.5,29.02) 36.2,29.73 36.2,32.02 v1(34.96,33.27)
  BOTTOM w0.102: Q8.2 35.38,32.78 35.36,32.76 R99.2 34.8,33.11 v1(34.96,33.27) ; U14.11 32.76,25.03 34.69,26.96 34.69,27.96 35.5,28.77 v1(35.5,29.02)
GND_EN9: length 13.1
  TOP w0.102: v1(7.95,28.64) 8.16,28.43 8.95,28.43 v1(9.13,28.61)
  BOTTOM w0.102: Q9.2 2.16,30.75 1.93,30.52 1.93,30.38 1.72,30.17 R108.2 1.52,29.96 1.12,29.56 1.12,29.05 1.27,28.89 1.73,28.89 2.04,29.2 7.39,29.2 v1(7.95,28.64) ; U17.14 9.06,28.54 v1(9.13,28.61)
GND_EN10: length 13.5
  TOP w0.102: v1(7.36,28.65) 7.84,28.18 9.34,28.18 v1(9.75,28.58)
  BOTTOM w0.102: Q10.2 2.08,27.96 1.96,27.84 1.96,27.51 1.72,27.27 R105.2 1.5,28.35 2.13,28.98 7.04,28.98 v1(7.36,28.65) ; U17.13 9.71,27.91 9.75,27.94 v1(9.75,28.58)
GND_EN11: length 15.4
  BOTTOM w0.102: Q11.2 2.1,21.63 1.82,21.35 R106.2 1.2,21.75 1.2,24.17 1.68,24.65 7.75,24.65 8.92,25.82 10.11,25.82 10.36,26.07 U17.12
GND_EN12: length 16
  BOTTOM w0.102: U17.11 11.01,26.07 10.54,25.6 9.24,25.6 7.09,23.45 7.09,22.15 5.01,20.07 2.01,20.07 1.59,19.65 R107.2 2.13,18.81 2.16,18.84 Q12.2
GND_EN13: length 14.3
  BOTTOM w0.102: U18.14 9.44,10.92 5.8,14.56 5.39,14.56 5.1,14.27 1.94,14.27 1.42,14.78 1.42,15.85 R113.2 1.61,16.05 Q13.2
GND_EN14: length 13.9
  TOP w0.102: v1(10.09,11.11) 10.07,11.1 v1(8.03,11.1)
  BOTTOM w0.102: v1(8.03,11.1) 8.03,11.63 7.43,12.24 5.26,12.24 4.85,11.84 1.99,11.84 1.62,12.21 R114.2 1.63,13.25 Q14.2 ; U18.13 v1(10.09,11.11)
GND_EN15: length 12.9
  TOP w0.102: v1(7.41,10.27) v1(10.59,10.27)
  BOTTOM w0.102: v1(7.41,10.27) 6.69,9.55 5.53,9.55 5.4,9.43 3.99,9.43 3.73,9.17 2.37,9.17 1.56,9.99 R115.2 1.56,10.46 Q15.2 ; U18.12 10.74,10.12 v1(10.59,10.27)
GND_EN16: length 15
  BOTTOM w0.102: U18.11 11.39,8.23 11.03,7.87 9.79,7.87 9.43,7.51 9.43,6.76 8.67,6 1.86,6 1.54,6.32 R116.2 1.75,7.66 1.75,7.66 Q16.2
GND_OTG_CONN: length 27.1
  TOP w0.381: v1(22.18,7.26) 22.18,7.67 CM1.4 ; J3.5 18.42,4.12 18.23,4.31
  TOP w0.508: 22.54,3.17 23.65,3.17 24.39,2.43 J3.9 ; 22.54,3.17 J3.7 ; 22.54,3.17 20.82,1.45 J3.10 19.82,1.45 18.23,3.04 16.71,3.04 16.33,2.66 16.33,1.54 J3.8 ; J3.6 18.23,4.31
  BOTTOM w0.254: C49.1 21.04,1.85 20.83,2.06 C48.1
  BOTTOM w0.33: 22.18,6.84 v1(22.18,7.26)
  BOTTOM w0.508: J3.6 17.15,4.45 16.33,3.63 16.33,2.82 16.24,2.73 J3.8 ; 20.89,2 20.89,2.73 MOV3.1 22.5,4.41 J3.7 22.54,6.25 22.18,6.61 22.18,6.84
V1P1: length 20.7
  TOP w0.178: U1.41 13.2,33.37 13.2,33.81 13.57,34.18 13.57,34.38 v1(13.77,34.58) ; U1.41 13.45,33.12 U1.41 ; U1.59 16.56,27.31 v1(17.07,27.82) ; v1(16.31,34.95) 16.14,34.95 U1.33
  TOP w0.305: U1.41 13.45,33.12 14.53,32.03 14.53,31.66 15.43,30.76 16.09,30.76 v1(16.34,30.51)
  BOTTOM w0.178: v1(17.07,27.82) 17.07,27.88 17.01,27.93 17.01,28.2 C20.1
  BOTTOM w0.203: 16.86,34.87 16.39,34.87 16.34,34.92
  BOTTOM w0.254: TP6.1 16.9,29.93 16.83,30 16.4,30 ; v1(13.77,34.58) 13.8,34.56 13.8,34.56 14.15,34.21 C28.1
  BOTTOM w0.305: 17.1,34.63 16.86,34.87 ; 17.1,34.63 18.32,33.41 18.32,32.2 16.76,30.63 16.76,30.62 16.63,30.49 16.36,30.49 v1(16.34,30.51) 16.34,30.05 16.4,30 15.78,29.4 15.64,29.26 15.64,28.48 16.29,27.82 v1(17.07,27.82) ; 17.1,34.63 C27.1 ; 16.34,34.92 v1(16.31,34.95)
V1P8: length 16.3
  TOP w0.102: U1.25 17.17,38.45 v1(17.17,38.73)
  TOP w0.203: 20.13,36.68 20.28,36.68 20.29,36.67 U1.18 ; U1.28 17.12,36.8 U1.28 ; U1.28 17.6,36.32 v1(18.14,36.32) ; U1.42 12.78,33.22 12.78,33.32 ; U1.19 19.95,36.91
  TOP w0.254: 12.78,33.32 12.64,33.46 12.64,33.84 v1(12.88,34.08) 12.61,34.34 12.61,34.49 12.2,34.9 10.67,34.9 10.51,35.06 10.51,35.9 10.98,36.37 v1(11.31,36.37) ; 19.95,36.91 19.95,36.85 20.13,36.67
  TOP w0.305: 20.13,36.67 v1(20.19,36.61)
  BOTTOM w0.102: v1(17.17,38.73) 17.31,38.59 C23.1 ; 20.59,36.5 20.13,36.5 20.14,36.49 20.14,36.18
  BOTTOM w0.254: C19.1 13.11,33.7 13.11,33.84 v1(12.88,34.08)
  BOTTOM w0.305: TP7.1 v1(18.14,39.48)
  BOTTOM w0.381: v1(11.31,36.37) 11.31,36.76 11.27,36.79 v1(11.27,38.42) ; 20.59,36.5 20.85,36.23
  vias: v1(18.26,36.79) v1(18.77,36.67)
V1P8O: length 2.9
  TOP w0.305: C17.1 13.37,37.21 13.33,37.26 L3.2
  TOP w0.508: L3.2 12.67,38.19 12.66,38.2 FB9.1
V3P3: length 115.6
  TOP w0.2: U1.63 18.1,26.56
  TOP w0.203: v1(17.4,27.39) 17.22,27.39 U1.60
  TOP w0.254: 18.1,26.56 18.1,26.78 18.1,26.79 v1(18.1,26.9) ; 17.38,27.37 v1(17.4,27.39) ; v1(3.63,38.88) 3.67,38.92 Y2.4 5.62,39.61 R25.1 ; U1.87 24.85,31.33 24.34,31.33 24.2,31.2 v1(24.03,31.2) ; U1.51 14.75,30 v1(14.93,30) ; v1(21.84,28.69) 22.03,28.5 22.03,28.5 U1.77 ; J1.1 27.77,36.7 27.45,37.03 v1(26.96,37.03) ; R27.1 26.28,36.07 v1(26.43,36.23) ; R5.1 12.78,26.29 12.54,26.05 v1(12.54,24.87) ; 25.86,36.86 25.97,36.97 v1(26.36,36.97) ; v1(16.58,28.28) 16.58,27.88 U1.58 ; v1(25.15,33.89) 24.86,33.89 U1.5 ; U1.73 20.9,27.37 20.9,27.37 20.71,27.55 ; 20.8,16.15 20.96,16.15 v1(21.45,15.66) ; R7.1 13.85,24.86 13.85,23.66 v1(13.73,23.54) 13.49,23.31 13.49,22.56 13.88,22.18 v1(13.88,21.48) 13.88,21.15 13.9,21.13 R6.1 ; U1.34 15.02,35.51 v1(14.42,35.51)
  TOP w0.305: R30.1 25.86,36.86 R29.1
  TOP w0.33: R54.1 37.97,1.85 38.23,1.59 v1(38.23,1.57)
  TOP w0.381: v1(38.69,7.47) 38.97,7.19 38.97,5.13 v1(38.41,4.58) ; v1(4.07,35.12) 4.64,35.69 4.64,37.59 4.86,37.81 4.86,38.85 Y2.4 6.41,37.45 8.35,37.45 9.58,36.21 9.58,33.7 10.46,32.82 10.62,32.82 10.64,32.81
  TOP w0.762: 21.92,15.21 21.62,14.91 21.62,14.79 v1(23.3,13.11) 23.3,11.95 22.84,11.49 22.84,11.25 v1(22.43,10.84)
  BOTTOM w0.102: v1(21.45,15.66) 21.45,15.91 21.43,15.94 TP2.1 ; 25.15,34.35 25.1,34.3
  BOTTOM w0.254: 25.14,35.62 25.24,35.71 25.24,35.94 25.63,36.33 25.63,36.94 26.09,37.4 26.59,37.4 v1(26.96,37.03) ; v1(3.63,38.88) C29.1 ; v1(4.07,35.12) 1.6,35.12 1.34,34.87 FB8.1 1.34,33.45 1.1,33.21 C91.1 ; v1(21.84,28.69) 21.45,29.08 21.44,29.08 C8.1 ; FB7.1 26.25,14.77 C84.1 ; C10.1 15.26,30.33 v1(14.93,30) ; C9.1 16.48,28.68 16.48,28.45 16.58,28.35 v1(16.58,28.28) ; 25.1,34.3 C3.1 ; v1(13.43,32.05) 13.43,32.29 15.22,34.07 15.22,34.72 C13.1 14.78,35.15 v1(14.42,35.51)
  BOTTOM w0.381: v1(12.54,24.87) 12.07,24.4 U2.8 ; v1(26.36,36.97) 26.43,36.9 v1(26.43,36.23) 26.43,35.9 26.94,35.39 26.94,34.69 26.86,34.61 v1(26.86,34.22) ; D10.2 39.59,7.75 38.98,7.75 v1(38.69,7.47)
  BOTTOM w0.5: 25.6,2.92 25.6,1.37 26.23,0.74 27.03,0.74 ; 25.06,3.47 24.74,3.79 24.74,5.11 23.13,6.72 23.13,8.36
  BOTTOM w0.508: C16.1 26.49,30.29 v1(26.49,30.3) ; v1(38.41,4.58) 38.41,3.87 38.84,3.44 38.84,2.18 v1(38.23,1.57) 37.4,0.74 27.03,0.74 ; 13.25,23.41 13.25,23.41 U2.8 ; v1(25.15,33.89) 25.15,34.35 25.24,34.44 25.24,35.71 ; 21.48,9.59 21.9,9.59 23.13,8.36 ; 25.6,2.92 25.06,3.47 ; FB7.1 25.05,14.77 24.49,14.21 24.49,14.13 23.8,13.43 23.62,13.43 v1(23.3,13.11)
  BOTTOM w0.762: v1(22.43,10.84) 22.02,10.43 22.02,10.12 21.48,9.59 21.07,9.18 16.39,9.18 15.63,9.94 15.63,14.18
  vias: v1(13.84,23.12) v1(23.49,31.3) v1(23.46,30.79) v1(23.94,30.71) v1(26.11,31.9) v1(26.18,31.32) v1(26.69,31.96) v1(26.71,31.32)
V3P3_EN: length 6.4
  TOP w0.254: R63.2 23.91,8.25
  TOP w0.33: C96.2 28.53,10.52 27.86,10.52 27.61,10.27 U7.1 27.17,9.25 26.51,8.58 24.23,8.58 23.91,8.25
V3P3_FB: length 3.3
  TOP w0.305: R64.2 29.18,8.51 29.16,8.49 R65.1 27.42,8.49 27.17,8.24 U7.5
V3P3_OUT: length 10.3
  TOP w0.254: L4.2 26.3,14.28 27.41,13.17 27.41,12.29 29.21,10.48 29.21,9.83 29.63,9.4 R64.1
  BOTTOM w0.5: C51.1 26,12.93 v1(25.15,13.78)
V5P0_VIN: length 1.1
  BOTTOM w0.5: v1(25.91,6.64) 25.64,6.91 C50.1
VBUS_OTG: length 40.2
  TOP w0.102: CM1.2 18.55,9.19 17.74,10 17.74,10.72 17.41,11.06 16.99,11.06 16.07,11.99 16.07,13.88 16.49,14.3 16.71,14.3 16.89,14.48 16.89,14.81 15.56,16.14 15.56,23.38 15.27,23.68 15.27,24.5 16.35,25.58 16.35,25.95 17.12,26.72 U1.61
  TOP w0.508: CM1.2 21.38,9.97 ; 21.38,9.97 21.38,11.14 21.72,11.48 21.72,12.48 21.21,12.99 U8.5 ; 21.38,9.97 23.35,9.97 v1(24.17,9.15)
  BOTTOM w0.5: v1(24.17,9.15) 24.17,6.66 25.62,5.2 25.82,5.2 26.65,4.37 R60.1 26.69,3.71 26.9,3.5 J2.3
VBUS_OTG_CONN: length 11.1
  TOP w0.381: 21.62,5.16 J3.1 ; v1(21.38,7.25) 21.38,7.78 CM1.1
  TOP w0.508: v1(21.62,5.4) 21.62,5.16
  BOTTOM w0.102: 19.59,2.11 19.5,2.02
  BOTTOM w0.254: C49.2 19.66,1.86 19.5,2.02 ; C48.2 19.96,2.11 19.59,2.11
  BOTTOM w0.508: 19.5,2.02 19.5,2.93 MOV3.2 19.29,4.89 19.8,5.4 v1(21.62,5.4) 21.62,6.09 21.38,6.33 v1(21.38,7.25)
VCC_FLEX1: length 84.3
  TOP w0.102: 28.49,15.58 C86.1 ; 28.52,15.16 v1(28.45,15.08)
  TOP w0.254: v1(28.42,18.76) 28.42,18.43 28.47,18.38 28.47,16.31 28.61,16.17 28.61,15.87 28.49,15.75 28.49,15.58 ; C86.1 28.52,15.16
  TOP w0.33: v1(34.12,31.18) 33.43,30.49 29.74,30.49 28.87,29.62 v1(28.49,29.62)
  TOP w0.381: v1(28.24,27.72) 28.24,28.35 v1(28.49,28.6)
  TOP w0.508: v1(33.59,33.3) 34.14,33.85 38.44,33.85 38.58,33.72 v1(39.03,33.72) 39.47,33.28 39.47,31.05 38.49,30.07 v1(38.49,29.19) 38.93,28.75 38.93,28.03 v1(38.61,27.71) 39.47,26.85 39.47,25.15 v1(39.03,24.7) 39.39,24.35 39.39,22.12 v1(39.11,21.84) 39.43,21.52 39.43,19.43 v1(39.09,19.1) 39.69,18.49 39.69,16.9 v1(39.12,16.32) 39.44,16 39.44,13.79 v1(39.12,13.47) ; U15.5 28.79,22.14 v1(29.19,21.74)
  BOTTOM w0.102: 34.11,31.58 C87.1
  BOTTOM w0.254: 34.11,31.19 34.11,31.58 ; U14.16 28.57,24.14 28.56,24.13 28.07,24.13 ; U13.16 28.94,14.78 28.64,15.08 v1(28.45,15.08)
  BOTTOM w0.305: v1(28.49,29.62) v1(28.49,28.6)
  BOTTOM w0.33: Q6.4 38.7,26.93 38.72,26.92 R93.1 ; Q1.4 38.78,12.96 38.8,12.95 R90.1 v1(39.12,13.47) ; v1(39.09,19.1) 39.12,19.07 R85.1 38.8,18.53 38.78,18.55 Q3.4 ; R94.1 33.21,32.76 33.2,32.78 Q7.4 ; v1(39.11,21.84) 39.12,21.83 R86.1 38.33,21.33 38.31,21.35 Q4.4 ; Q8.4 38.53,33.28 38.55,33.27 R95.1 38.86,33.55 v1(39.03,33.72) ; Q5.4 38.58,24.14 38.6,24.12 R92.1 39.12,24.62 v1(39.03,24.7) ; v1(39.12,16.32) R84.1 38.72,15.74 38.7,15.76 Q2.4
  BOTTOM w0.381: v1(38.49,29.19) 37.42,29.19 36.96,28.73 U16.5 ; v1(34.12,31.18) 34.11,31.19 ; v1(28.24,27.72) 28.24,25.82 27.45,25.03 27.45,24.4 27.73,24.13 28.07,24.13 27.78,23.84 27.78,23.28 28.91,22.16 28.91,22.02 v1(29.19,21.74) 28.47,21.02 28.47,18.81 v1(28.42,18.76) 28.35,18.7 25.42,18.7 23.8,17.08 C85.1 ; R93.1 39.12,27.2 v1(38.61,27.71) ; 34.11,31.58 33.99,31.7 33.99,32.62 33.93,32.68 33.9,32.68 33.83,32.76 R94.1 33.53,33.24 v1(33.59,33.3)
  BOTTOM w0.508: C85.1 24.24,16 24.39,16.15 FB7.2
VCC_FLEX2: length 80.4
  TOP w0.203: 11.29,9.98 11.29,10.88
  TOP w0.254: v1(13.48,11.85) 12.99,11.37 11.77,11.37 11.29,10.88 ; v1(6.19,32.25) 5.86,32.25 5.73,32.38 v1(2.89,32.38) ; v1(6.24,33.36) 8.36,33.36 8.65,33.64 v1(8.88,33.87) ; 11.29,9.98 10.79,9.48 v1(7.5,9.48)
  TOP w0.381: v1(8.16,13.6) 11.32,13.6 13.34,15.62 U20.5 ; v1(6.19,30.7) 5.43,30.7 4.96,30.24 4.96,29.05 5.44,28.56 5.8,28.56 v1(6.08,28.28) 5.9,28.11 5.9,26.24 5.1,25.44 5.1,23.28 v1(5.46,22.92) 5.77,22.61 5.77,20.98 5.6,20.82 v1(5.6,20.16) 5.6,19.54 5.66,19.49 5.66,17.61 5.68,17.59 v1(5.68,17.2) 5.4,16.92 5.4,15.77 v1(6.23,14.94) 5.64,14.35 v1(5.64,14.2) 5.36,13.92 v1(5.36,11.83) 5.12,11.59 5.12,9.52 v1(5.65,8.98)
  BOTTOM w0.254: U18.16 7.83,9.15 v1(7.5,9.48) 7,8.98 v1(5.65,8.98) ; C89.1 13.68,12.06 v1(13.48,11.85) ; 6.19,30.77 v1(6.19,32.25) 6.19,32.98 6.24,33.03 v1(6.24,33.36) ; C88.1 11.18,33.77 9.38,33.77 9.27,33.87 v1(8.88,33.87)
  BOTTOM w0.305: 6.84,28.28 7,28.12 7.58,28.12 7.76,27.94 U17.16
  BOTTOM w0.33: 6.84,28.28 6.55,28.28 6.54,28.28 v1(6.08,28.28) R102.1 5.24,28.28 5.07,28.45 Q10.4 ; v1(8.16,13.6) 7.58,13.6 v1(6.23,14.94) ; v1(5.68,17.2) 5.59,17.11 R109.1 5.13,16.74 4.94,16.55 Q13.4 ; Q9.4 4.99,31.25 5.16,31.08 R101.1 5.89,31.08 6.19,30.77 ; Q15.4 5.1,10.96 5.34,11.19 R111.1 5.66,11.54 v1(5.36,11.83) ; v1(5.64,14.2) 5.66,14.19 R110.1 5.34,13.73 5.32,13.75 Q14.4 ; 3.64,22.97 3.64,22.6 4.11,22.13 Q11.4 4.89,22.13 5.12,22.37 R103.1 5.66,22.72 v1(5.46,22.92) ; Q12.4 4.75,19.34 4.99,19.58 R104.1 5.6,19.63 v1(5.6,20.16) ; v1(5.65,8.98) 5.65,8.4 R112.1 5.34,8.4 5.1,8.16 Q16.4
  BOTTOM w0.381: U19.5 3.64,22.97
  BOTTOM w0.457: v1(2.89,32.38) 2.95,32.44 C90.1 2.96,33.01 2.96,34.14 2.94,34.15
  BOTTOM w0.508: 2.94,34.15 FB8.2 ; v1(6.19,30.7) 6.19,30.77
VDD11_F_88: length 3.4
  TOP w0.254: v1(25.58,31.78) 25.61,31.75 25.61,31.36 U1.88
  BOTTOM w0.254: v1(25.58,31.78) 25.58,32.11 25.85,32.38 26.53,32.38 26.61,32.46 26.61,32.46 26.65,32.5 C93.1 26.65,33
  BOTTOM w0.381: 26.65,33 26.65,33.27 C2.1
VDD18_F_86: length 3
  TOP w0.254: v1(25.34,30.14) 25.34,30.27 U1.86
  BOTTOM w0.254: v1(25.34,30.14) 24.89,30.14 24.71,29.96 C92.1 25.01,29.34 25.18,29.5 C1.1
VDD33_20: length 3
  TOP w0.203: U1.20 20.48,38 20.92,38 v1(21.41,37.5)
  BOTTOM w0.102: v1(21.41,37.5) 21.35,37.57 21.35,37.72 21.18,37.88 21.16,37.88
  BOTTOM w0.254: C4.1 20.93,37.39 21.04,37.5 v1(21.41,37.5)
CLK32K: length 2.1
  TOP w0.152: Y2.3 3.84,36.91 3.84,36.48 3.59,36.23 R128.2
CONN_DM: length 4.3
  TOP w0.3: CM2.1 19.74,7.33 19.64,7.22 19.64,6.81 20.86,5.59 20.86,4.93 20.97,4.83 J3.2
CONN_DP: length 4.3
  TOP w0.3: J3.3 20.32,4.83 20.42,4.93 20.42,5.41 19.2,6.63 19.2,7.22 19.09,7.33 CM2.2
CONN_ID: length 4.3
  TOP w0.102: CM2.3 18.44,6.26 19.67,5.04 J3.4
CP1: length 37.2
  TOP w0.102: v1(30.3,22.87) 30.89,23.45 35.45,23.45 36.06,24.06 36.06,26.24 34.27,28.03 31.2,28.03 v1(30.81,28.42) ; U1.16 21.6,36.85 23.86,36.85 24,36.71 v1(24.26,36.71)
  BOTTOM w0.102: v1(30.3,22.87) 30.3,21.09 30.24,21.03 U13.3 ; v1(24.26,36.71) 24.08,36.89 24.08,37.07 24.57,37.56 24.93,37.56 25.68,38.31 27.6,38.31 28.14,37.77 28.14,32.25 29.33,31.05 30.35,31.05 30.81,30.59 U14.3 v1(30.81,28.42)
CP2: length 43.2
  TOP w0.102: v1(14.75,22.64) 14.75,22.6 14.93,22.43 14.93,18.03 13.93,17.03 12.3,17.03 11.49,16.23 9.28,16.23 v1(9.05,16) ; v1(6.14,16.17) 6.14,20.12 5.95,20.31 5.95,20.67 6.19,20.91 6.19,22.77 5.45,23.51 5.45,25.24 6.25,26.03 6.25,27.83 6.51,28.09 6.51,28.66 6.91,29.06 8.3,29.06 8.4,28.96 v1(8.65,28.96) ; v1(18.53,26.45) 19.03,25.95 19.03,25.85 U1.67
  BOTTOM w0.102: v1(8.65,28.96) 8.41,29.21 8.41,31.07 9.06,31.72 U17.3 ; U18.3 9.44,15.61 v1(9.05,16) 8.87,16.18 6.52,16.18 6.52,16.17 v1(6.14,16.17) ; v1(14.75,22.64) 15.01,22.9 15.01,24.05 15.63,24.68 15.83,24.68 17.6,26.45 v1(18.53,26.45)
D_1_4: length 21.9
  TOP w0.102: U1.15 21.15,35.84 21.15,35.25 21.74,34.66 21.74,34.15 v1(22.2,33.69) ; v1(28.52,23.68) 28.09,23.68 25.1,26.67 25.1,26.88 24.64,27.34 v1(23.95,27.34)
  BOTTOM w0.102: v1(28.52,23.68) 29.02,23.18 29.78,23.18 29.93,23.02 29.93,21.22 29.59,20.88 U13.2 ; v1(23.95,27.34) 22.96,28.33 22.96,28.92 21.74,30.14 21.74,33.23 v1(22.2,33.69)
D_5_8: length 17
  TOP w0.102: v1(24.66,37.09) 24.41,37.09 24.39,37.11 21.29,37.11 U1.17 ; U1.17 20.98,36.8 U1.17
  BOTTOM w0.102: U14.2 30.16,30.69 30.02,30.83 29.15,30.83 27.92,32.06 27.92,37.57 27.38,38.1 25.79,38.1 24.96,37.27 24.84,37.27 v1(24.66,37.09)
D_9_12: length 21.7
  TOP w0.102: v1(16.13,37.05) 15.51,37.05 15.22,36.76 13.74,36.76 13.43,36.45 v1(11.85,36.45) ; U1.6 23.68,33.28 23.68,33.28 23.6,33.2 22.18,33.2 21.39,33.99 21.39,34.68 20.26,35.81 17.14,35.81 16.92,35.59 v1(16.92,35.56)
  BOTTOM w0.102: v1(16.92,35.56) 16.63,35.86 16.63,36.55 v1(16.13,37.05) ; v1(11.85,36.45) 11.73,36.33 11.73,35.26 11.32,34.85 9.28,34.85 8.41,33.98 U17.2
D_13_16: length 39.6
  TOP w0.102: U1.47 12.53,30.04 12.28,30.04 11.78,29.55 11.45,29.55 11.28,29.72 11.28,30.32 10.85,30.75 v1(10.85,30.97) ; v1(1.88,14.88) 0.81,15.95 0.81,27.24 2.43,28.87 2.43,29.64 4.56,31.77 9.63,31.77 10.14,31.26 10.14,31 9.94,30.8 v1(9.94,30.55)
  BOTTOM w0.102: v1(9.94,30.55) 10.43,30.55 v1(10.85,30.97) ; U18.2 8.79,13.53 8.43,13.17 7.47,13.17 5.88,14.77 5.31,14.77 5.05,14.51 2.25,14.51 v1(1.88,14.88)
EN_32K: length 1.9
  TOP w0.254: R25.2 5.14,40.65 4.26,40.65 3.73,40.12 Y2.1
GPIO_25: length 15.4
  TOP w0.102: v1(3.05,35.6) 3.05,35.33 3.31,35.06 R128.1
  TOP w0.152: R128.1 3.59,34.97 5.6,32.96 8.79,32.96 10.39,31.37 10.39,30.88 11.02,30.26 11.02,29.59 11.32,29.29 11.84,29.29 12.31,29.75 12.73,29.75 12.8,29.83 13.44,29.83 U1.49
  BOTTOM w0.102: TP5.1 2.99,35.59 v1(3.05,35.6)
GPIO_27: length 2
  TOP w0.102: U1.66 18.64,25.2 18.83,25.02 18.83,24.46 v1(18.64,24.27)
  BOTTOM w0.102: v1(18.64,24.27) TP4.1
ISENSE: length 1.5
  TOP w0.102: v1(21.16,28.09) 21.16,27.67 U1.74
  BOTTOM w0.102: R3.2 20.85,28.41 v1(21.16,28.09)
LED1: length 29.9
  TOP w0.102: U1.75 22.16,27.23 22.16,26.44 25.03,23.57 25.03,20.35 27.11,18.27 27.11,14.36 27.93,13.54 27.93,12.51 29.66,10.78 34.52,10.78 37.2,8.1 v1(37.2,7.47)
  BOTTOM w0.102: R48.2 v1(37.2,7.47)
LED2: length 31.6
  TOP w0.102: v1(37.24,6.56) 37.65,6.98 37.65,8.02 34.66,11.01 29.75,11.01 28.17,12.59 28.17,13.68 27.32,14.54 27.32,18.35 25.3,20.37 25.3,23.6 22.44,26.46 22.44,27.52 U1.76
  BOTTOM w0.102: v1(37.24,6.56) 37.24,6.3 37.34,6.2 R49.2
LED3: length 28.9
  TOP w0.102: v1(35.85,8.94) 34.23,10.56 29.56,10.56 27.72,12.41 27.72,13.35 26.89,14.19 26.89,18.13 24.75,20.27 24.75,23.52 22.17,26.1 21.03,26.1 U1.71
  BOTTOM w0.102: R118.2 37.13,8.96 37.11,8.94 v1(35.85,8.94)
MCI_TCK: length 11.8
  TOP w0.102: U1.9 23.85,35.15 25.3,35.15 R36.1 25.38,35.46 25.46,35.54 26.88,35.54 27.51,34.91 27.51,31.82 27.84,31.48 29.38,31.48 29.61,31.71 J1.4
MCI_TDI: length 17.4
  TOP w0.102: J1.8 32.15,31.84 32.05,31.73 31.11,31.73 30.44,31.06 28.08,31.06 v1(27.88,30.86) ; v1(27.55,36.14) 27.29,36.14 26.84,36.59 26.19,36.59 26.05,36.45 25.59,36.45 25.4,36.64 R29.2 25.21,36.67 25.21,36.66 24.14,35.58 23.16,35.58 U1.11
  BOTTOM w0.102: v1(27.55,36.14) 27.71,35.97 27.71,31.02 v1(27.88,30.86)
MCI_TDO: length 12.5
  TOP w0.102: J1.6 30.88,31.83 30.33,31.27 27.72,31.27 27.29,31.69 27.29,34.64 27.11,34.82 25.51,34.82 25.38,34.7 R28.2 24.79,34.49 24.68,34.38 24.3,34.38 24.08,34.59 23.86,34.59 U1.8
MCI_TMS: length 10.9
  TOP w0.102: J1.2 28.34,31.82 28.23,31.7 27.94,31.7 27.75,31.89 27.75,35.02 27.01,35.76 25.5,35.76 25.39,35.86 R27.2 25.13,36.07 24.42,35.36 23.5,35.36 U1.10
MCI_TRST: length 10.1
  TOP w0.102: U1.12 22.85,35.84 24.05,35.84 25.03,36.82 25.03,37.5 25.17,37.64 R30.2 25.41,37.86 25.61,38.06 29.4,38.06 29.61,37.85 J1.3
OE1: length 43.8
  TOP w0.102: v1(34.52,12.42) 34.26,12.42 33.98,12.7 v1(33.98,13.9) ; U1.13 22.67,36.23 v1(23.22,36.23)
  BOTTOM w0.102: v1(34.52,12.42) 34.34,12.24 30.76,12.24 30.58,12.41 R100.2 29.72,13.11 29.59,13.25 U13.15 ; v1(33.98,13.9) 33.98,14.81 33.62,15.17 33.62,16.59 33.77,16.75 33.77,18.18 34.42,18.83 34.42,20.39 33.36,21.45 31.08,21.45 30.86,21.67 30.86,22.82 30.38,23.3 30.37,23.3 30.16,23.51 U14.15 30.16,25.79 28.68,27.27 28.68,27.85 28.05,28.49 28.05,29.84 27.29,30.6 27.29,35.56 26.92,35.93 26.92,36.46 27.37,36.91 27.37,37.36 27.04,37.69 25.97,37.69 25.32,37.04 25.32,36.5 24.86,36.05 23.4,36.05 v1(23.22,36.23)
OE2: length 61.4
  TOP w0.102: v1(1.29,9.55) 0.41,10.42 0.41,16.12 0.56,16.27 0.56,27.96 1.52,28.91 v1(1.52,29.34) ; v1(9.22,7.88) 8.03,7.88 6.88,6.74 5.58,6.74 4.76,7.56 v1(4.76,8.99) ; v1(5.19,36.49) 5.72,37.02 7.63,37.02 v1(9,35.65) ; U1.36 14.45,34.94 12.79,34.94 12.5,35.24 11.21,35.24 v1(10.98,35.47) ; v1(4.96,32.96) 5.22,32.69 6.32,32.69 v1(6.81,32.19)
  BOTTOM w0.102: v1(1.29,9.55) 2,8.84 3.82,8.84 3.98,8.99 v1(4.76,8.99) ; v1(10.98,35.47) 9.46,35.47 9.28,35.65 v1(9,35.65) ; v1(9.22,7.88) 9.2,7.86 R117.2 8.76,8.27 8.79,8.3 U18.15 ; 6.84,29.45 6.81,29.47 v1(6.81,32.19) ; 6.84,29.45 7.66,29.45 8.41,28.69 U17.15 ; 6.84,29.45 1.88,29.45 1.77,29.34 v1(1.52,29.34) ; v1(4.96,32.96) 4.78,33.14 4.78,36.08 v1(5.19,36.49)
PIN1: length 29.8
  TOP w0.102: v1(27.12,19.35) 27.52,18.95 27.52,14.86 29.61,12.77 29.61,12.1 29.76,11.95 J6.1 ; v1(26.81,23.09) U15.1 25.99,23.42 23.04,26.37 23.04,28.05 U1.78
  TOP w0.33: J6.1 33.68,11.95 34.05,11.58 36.48,11.58 36.67,11.77 36.68,11.77 v1(37.01,12.1)
  BOTTOM w0.102: v1(27.12,19.35) 27.43,19.67 27.43,22.47 v1(26.81,23.09)
  BOTTOM w0.33: v1(37.01,12.1) 37.14,11.96 Q1.6
  BOTTOM w0.381: Q1.3 36.78,12.96 37.01,12.74 v1(37.01,12.1)
PIN2: length 30.5
  TOP w0.102: U1.79 23.29,28.37 23.29,26.5 26.24,23.55 27.1,23.55 27.27,23.39 27.27,22.02 26.44,21.19 U15.3 25.99,20.87 25.82,20.69 25.82,20.21 26.24,19.79 27.27,19.79 27.73,19.32 27.73,15.05 28.3,14.49 J6.2
  TOP w0.381: J6.2 33.71,14.49 34.23,15.02 34.23,15.2 v1(34.51,15.48)
  BOTTOM w0.33: Q2.3 35.76,15.76 35.74,15.78 ; 35.74,15.78 36.78,15.78 37.03,15.53 37.03,14.94 37.22,14.76 Q2.6 ; 35.74,15.78 34.89,15.78 34.86,15.74 34.78,15.74 v1(34.51,15.48)
PIN3: length 25.7
  TOP w0.102: U1.80 23.58,28.65 23.58,26.55 26.34,23.78 27.27,23.78 27.53,23.52 27.53,21.6 27.94,21.19 U15.4 28.39,20.87 29.63,19.63 29.63,17.16 29.76,17.03 J6.3
  TOP w0.381: v1(37.1,17.17) 36.82,17.45 34.53,17.45 34.11,17.03 J6.3
  BOTTOM w0.33: Q3.6 37.66,17.5 37.33,17.17 v1(37.1,17.17) 37.05,17.23 37.05,18.32 36.81,18.55 Q3.3
PIN4: length 22.8
  TOP w0.102: 28.94,23.09 28.94,22.58 29.66,21.86 29.66,20.18 30.26,19.57 J6.4 ; 28.94,23.09 U15.6 ; 28.94,23.09 28.94,23.96 28.71,24.19 27.98,24.19 25.34,26.83 25.34,27.45 U1.81
  TOP w0.381: J6.4 33.71,19.57 34.4,20.26 v1(34.4,20.98)
  BOTTOM w0.33: v1(34.4,20.98) 34.76,21.35 Q4.3 36.91,21.35 37.07,21.18 37.07,20.56 37.28,20.35 Q4.6
PIN5: length 26.5
  TOP w0.102: U1.82 25.62,27.73 25.62,26.86 28.08,24.4 28.79,24.4 29.15,24.05 29.15,22.68 29.72,22.11 J6.5
  TOP w0.381: v1(35.09,27.8) 37.15,25.73 37.15,24.4 37.08,24.33 v1(37.08,23.94) 36.8,23.66 36.8,23.57 36.26,23.02 34.25,23.02 33.34,22.11 J6.5
  BOTTOM w0.33: Q5.6 37.25,23.14 37.08,23.31 v1(37.08,23.94) 36.88,24.14 Q5.3
  BOTTOM w0.381: v1(35.09,27.8) 35.53,27.8 36.01,28.28 U16.6
PIN6: length 21.2
  TOP w0.102: J6.6 28.17,24.65 25.88,26.93 25.88,28.04 U1.83
  TOP w0.381: v1(35.13,24.37) 34.57,24.37 34.29,24.65 J6.6
  BOTTOM w0.33: 37.04,25.83 37.16,25.94 37.17,25.93 Q6.6
  BOTTOM w0.381: v1(35.13,24.37) 36.02,25.26 36.71,25.26 37.04,25.6 37.04,27.16 ; 37.04,27.16 36.82,26.93 36.41,26.93 Q6.3 ; 37.04,27.16 37.04,27.5 37.22,27.67 37.69,27.67 37.91,27.89 U16.4
PIN7: length 25.5
  TOP w0.102: U1.84 24.95,29.53 25.07,29.53 25.63,28.97 28.65,28.97 29.03,28.59 29.03,27.91 29.76,27.19 J6.7
  TOP w0.381: v1(33.22,31.37) 33.61,31.77 34.52,31.77 35.51,30.77 35.51,29.82 v1(35.08,29.39) ; v1(34.16,27.19) J6.7
  BOTTOM w0.33: 32.97,31.63 32.82,31.78 Q7.6 31.67,31.78 31.49,31.96 31.49,32.5 31.21,32.78 Q7.3
  BOTTOM w0.381: 32.97,31.63 v1(33.22,31.37) ; U16.3 37.91,30.06 37.54,29.7 37.11,29.7 36.94,29.53 35.22,29.53 v1(35.08,29.39) 34.81,29.11 34.81,28.7 34.16,28.05 v1(34.16,27.19)
PIN8: length 16.7
  TOP w0.102: J6.8 29.74,29.73 29.19,29.17 25.71,29.17 24.99,29.9 24.99,30.06 U1.85
  TOP w0.381: J6.8 33.71,29.73 34.34,30.37 v1(34.89,30.37)
  BOTTOM w0.381: Q8.6 36.96,32.28 36.79,32.11 ; 36.79,32.11 36.79,31.87 36.01,31.08 U16.1 35.57,30.37 v1(34.89,30.37) ; 36.79,32.11 36.79,33.22 36.73,33.28 Q8.3
PIN9: length 35.7
  TOP w0.102: U1.1 25.11,31.88 23.53,31.88 23.09,32.32 21.77,32.32 20.55,33.54 20.55,34.27 19.82,35 17.97,35 16.97,34 16.97,33.24 v1(16.62,32.89) ; J9.1 10.38,29.73 11.14,28.96 11.87,28.96 12.4,29.5 12.88,29.5 13.02,29.36 v1(13.27,29.36)
  TOP w0.381: v1(3.67,29.8) 3.67,28.66 2.11,27.09 v1(2.11,26.42) ; J9.1 6.93,29.73 6.79,29.59 5.8,29.59 v1(5.52,29.86)
  BOTTOM w0.102: v1(13.27,29.36) 13.66,29.75 13.66,30.63 14.51,31.48 14.51,32.07 15.6,33.16 16.35,33.16 v1(16.62,32.89)
  BOTTOM w0.33: U19.1 2.69,26.14 2.41,26.42 v1(2.11,26.42)
  BOTTOM w0.381: v1(5.52,29.86) 5.13,30.25 Q9.6 4.1,30.08 3.83,29.8 v1(3.67,29.8) 3.48,29.99 3.48,31.03 3.26,31.25 Q9.3
